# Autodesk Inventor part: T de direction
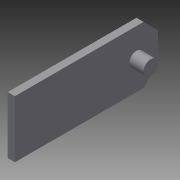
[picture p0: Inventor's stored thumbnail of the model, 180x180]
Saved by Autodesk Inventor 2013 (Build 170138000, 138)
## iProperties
Created: 2015-07
Part Number: T de direction
Material: Générique
Document SubType Name: Modeling
Designer: OL
Density: 1 g/cm^3
Author: OL
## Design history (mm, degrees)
sketch "Esquisse1"
  geometry: L1 (-40, 40)-(140, 40); L2 (160, 20)-(160, -20); L3 (140, -40)-(-40, -40); L4 (-40, -40)-(-40, 40); L5 (140, 40)-(160, 20); L6 (160, -20)-(140, -40); 1 further point
  constraints: 12 end point, 2 parallel, 1 horizontal, 1 perpendicular
  dimensions: "d2" = 80 distance of L3.end L1.start; "d3" = 200 distance between parallel lines of L4 L2; "d4" = 20 horizontal distance of L1.end L2.start; "d5" = 20 horizontal distance of L1.end L2.start; "d6" = 20 horizontal distance of L2.end L3.start; "d7" = 20 horizontal distance of L2.end L3.start; "d8" = 40 distance from line of L1 point (0, 0); "d9" = 40 distance from line of L4 point (0, 0)
extrude "Extrusion1" new body sketch "Esquisse1" distance "d10" = 10; taper "d11" = 0 deg
sketch "Esquisse2"
  geometry: L1 (20, 160)-(-20, 160) reference; C1 r 10 at (0, 130); 1 further point
  constraints: 1 centre point
  dimensions: "d12" = 20 diameter of C1; "d14" = 30 distance from line of L1 C1.centre
extrude "Extrusion2" join sketch "Esquisse2" distance "d15" = 20; taper "d16" = 0 deg
node "Solide1"
